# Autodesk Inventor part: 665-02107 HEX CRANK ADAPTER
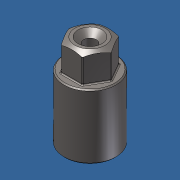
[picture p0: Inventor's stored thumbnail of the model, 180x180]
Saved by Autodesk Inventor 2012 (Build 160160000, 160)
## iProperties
Created: 2013-10
Part Number: 665-02107 HEX CRANK ADAPTER
Material: Default
Document SubType Name: Modeling
Designer: Admin
Density: 1 g/cm^3
Author: Admin
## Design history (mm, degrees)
node "665-02107 HEX CRANK ADAPTER1"
node "Base1"
body "Solid1"
